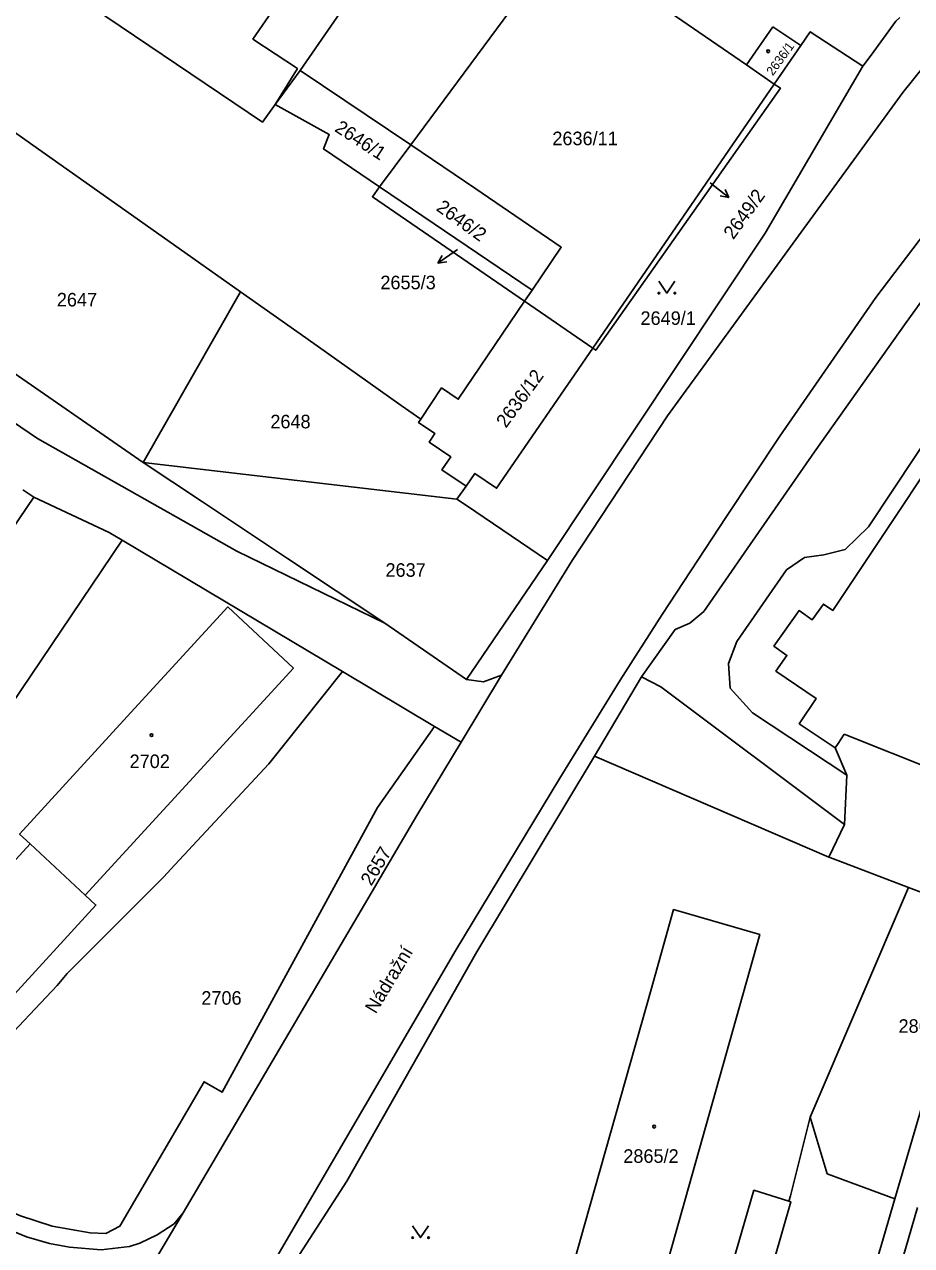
# Model space of a CAD drawing. Extents: x -527335 to -526256, y -1079142 to -1077836.
# Drawn here: x -527132.2 to -527020.7, y -1078877.1 to -1078723.7 of the extents above; entities that cross this region are included whole.
import ezdxf

# ---------------------------------------------------------------- set-up
doc = ezdxf.new("R2010")
doc.units = 0
for name, color, linetype in [('Hranice parcel', 7, 'Continuous'), ('Parcelní čísla', 7, 'Continuous'), ('Pop  PČ popisy', 7, 'Continuous'), ('Vnitřní kresba', 7, 'Continuous'), ('Značky budov', 7, 'Continuous'), ('Značky kultur', 7, 'Continuous')]:
    doc.layers.add(name, color=color, linetype=linetype)

msp = doc.modelspace()

# ---------------------------------------------------------------- linework, layer by layer
at = {"layer": 'Hranice parcel'}
for p, q in [((-527097.53, -1078729.48), (-527100.64, -1078733.75)), ((-527097.53, -1078729.48), (-527083.63, -1078738.83)), ((-527060.76, -1078764.37), (-527037.96, -1078731.19)), ((-527087.53, -1078744.11), (-527083.63, -1078738.83)), ((-527087.53, -1078744.11), (-527068.38, -1078757.06)), ((-527117.23, -1078778.72), (-527104.99, -1078757.3)), ((-527068.38, -1078757.06), (-527069.34, -1078758.47)), ((-527148.09, -1078757.41), (-527117.23, -1078778.72)), ((-527069.34, -1078758.47), (-527060.76, -1078764.37)), ((-527077.82, -1078783.31), (-527117.23, -1078778.72)), ((-527077.82, -1078783.31), (-527076.65, -1078781.68)), ((-527076.62, -1078805.97), (-527066.43, -1078791.03)), ((-527077.3, -1078813.84), (-527072.22, -1078805.43)), ((-527077.3, -1078813.84), (-527080.64, -1078811.86)), ((-527031.1, -1078828.29), (-527060.55, -1078815.59)), ((-527131.44, -1078826.61), (-527124.5, -1078833.07)), ((-527033.44, -1078860.94), (-527021.11, -1078832.09)), ((-526983.93, -1078846.24), (-527021.11, -1078832.09))]:
    msp.add_line(p, q, dxfattribs=at)
for points in [[(-527072.22, -1078805.43), (-527063.35, -1078791.03), (-527051.39, -1078772.86), (-527021.8, -1078732.24), (-527016.31, -1078725.38), (-526999.22, -1078705.77), (-526979.26, -1078684.5), (-526961.36, -1078666.17), (-526945.34, -1078649.61), (-526932.24, -1078641.62), (-526929.63, -1078639.61), (-526929.14, -1078637.23), (-526930.46, -1078635.68), (-526927.65, -1078633), (-526895.17, -1078602.34)], [(-527100.64, -1078733.75), (-527102.25, -1078735.96), (-527127.31, -1078719.02), (-527111.05, -1078694.45)], [(-527080.84, -1078705.04), (-527083.41, -1078706.65), (-527085.52, -1078706.27), (-527089.43, -1078704.54), (-527090.21, -1078705.74), (-527091.13, -1078707.66), (-527103.45, -1078725.55), (-527097.86, -1078729.26), (-527100.64, -1078733.75)], [(-527080.84, -1078705.04), (-527085.2, -1078711.65), (-527097.53, -1078729.48)], [(-527083.63, -1078738.83), (-527064.48, -1078712.94), (-527041.46, -1078728.79), (-527037.96, -1078731.19)], [(-527026.84, -1078728.96), (-527025.8, -1078727.55), (-527022.69, -1078723.31), (-527022.2, -1078722.85)], [(-526998.63, -1078724.92), (-527007.36, -1078735.07), (-527019.76, -1078750.86), (-527025.21, -1078757.99), (-527037.26, -1078775.41), (-527043.97, -1078785.5), (-527052.05, -1078797.8), (-527057.33, -1078806.06), (-527064.89, -1078818.36), (-527077.97, -1078839.97), (-527106.45, -1078888.73), (-527179.38, -1079013.92), (-527179.74, -1079015.3)], [(-527060.55, -1078815.59), (-527054.66, -1078805.64), (-527050.43, -1078799.71), (-527048.56, -1078798.89), (-527046.8, -1078797.42), (-527041.37, -1078789.55), (-527032.93, -1078777.37), (-527021.38, -1078761.15), (-527014.2, -1078751.18), (-527004.39, -1078737.66), (-526998.1, -1078729.59), (-526996.78, -1078727.49), (-526996.17, -1078726.12), (-526997.1, -1078724.79), (-526998.63, -1078724.92)], [(-527037.96, -1078731.19), (-527034.65, -1078726.37), (-527033.45, -1078724.63), (-527026.84, -1078728.96)], [(-527026.84, -1078728.96), (-527039.13, -1078749.94), (-527066.43, -1078791.03)], [(-527037.96, -1078731.19), (-527037.19, -1078731.69), (-527060.38, -1078764.63), (-527060.76, -1078764.37)], [(-527100.64, -1078733.75), (-527093.86, -1078737.51), (-527094.58, -1078739.34), (-527087.53, -1078744.11)], [(-527104.99, -1078757.3), (-527129.66, -1078739.88), (-527134.11, -1078736.73), (-527148.09, -1078757.41)], [(-527083.63, -1078738.83), (-527075.44, -1078744.34), (-527064.73, -1078751.68), (-527068.38, -1078757.06)], [(-527087.53, -1078744.11), (-527088.44, -1078745.34), (-527069.34, -1078758.47)], [(-527082.38, -1078773.28), (-527084.82, -1078771.55), (-527096.82, -1078763.08), (-527104.99, -1078757.3)], [(-527069.34, -1078758.47), (-527077.66, -1078770.78), (-527079.76, -1078769.36), (-527082.38, -1078773.28)], [(-527076.65, -1078781.68), (-527075.57, -1078780.1), (-527072.85, -1078781.96), (-527060.76, -1078764.37)], [(-527003.07, -1078773.49), (-527011.16, -1078768.09), (-527030.63, -1078797.3), (-527031.8, -1078796.49), (-527033.21, -1078798.48), (-527034.85, -1078797.32), (-527038.02, -1078801.77), (-527036.37, -1078802.94), (-527037.76, -1078804.91), (-527032.72, -1078808.35), (-527034.82, -1078811.52), (-527030.31, -1078814.54), (-527028.85, -1078818), (-527029.14, -1078824.18), (-527031.1, -1078828.29)], [(-527076.65, -1078781.68), (-527079.71, -1078779.62), (-527078.61, -1078778.01), (-527081.31, -1078776.16), (-527080.58, -1078775.08), (-527082.65, -1078773.68), (-527082.38, -1078773.28)], [(-527117.23, -1078778.72), (-527109.79, -1078783.67), (-527099.09, -1078790.78), (-527086.87, -1078798.91), (-527076.62, -1078805.97)], [(-527132.36, -1078782.16), (-527130.96, -1078783.09), (-527121.51, -1078787.51), (-527119.86, -1078788.49)], [(-527066.43, -1078791.03), (-527076.61, -1078784.13), (-527077.82, -1078783.31)], [(-527172.24, -1078856.19), (-527141.71, -1078814.86), (-527138.98, -1078816.71), (-527119.86, -1078788.49)], [(-527119.86, -1078788.49), (-527092.2, -1078804.98), (-527080.64, -1078811.86)], [(-527124.5, -1078833.07), (-527111.43, -1078818.8), (-527098.36, -1078804.54), (-527106.61, -1078796.85), (-527119.69, -1078811.12), (-527132.76, -1078825.39), (-527131.44, -1078826.61)], [(-527076.62, -1078805.97), (-527074.47, -1078806.26), (-527072.22, -1078805.43)], [(-527080.64, -1078811.86), (-527087.81, -1078822.05), (-527107.3, -1078857.78), (-527109.58, -1078856.49), (-527120.15, -1078874.63), (-527121.91, -1078875.54), (-527123.9, -1078875.45), (-527128.65, -1078874.62), (-527132.64, -1078873.34), (-527143.8, -1078868.59), (-527146.2, -1078867.57), (-527172.24, -1078856.19)], [(-527112.22, -1078872.94), (-527082.87, -1078823.07), (-527077.3, -1078813.84)], [(-527106.29, -1078891.74), (-527106.04, -1078891.29), (-527091.65, -1078868.97), (-527075.33, -1078840.18), (-527060.55, -1078815.59)], [(-527131.44, -1078826.61), (-527144.07, -1078840.4), (-527144.58, -1078840.95), (-527157.72, -1078855.29), (-527149.33, -1078862.84), (-527144.03, -1078857.05), (-527136.25, -1078848.56), (-527135.69, -1078847.95), (-527123.17, -1078834.29), (-527124.5, -1078833.07)], [(-527021.11, -1078832.09), (-527030.54, -1078828.5), (-527031.1, -1078828.29)], [(-527221.67, -1078833.78), (-527221.62, -1078835.3), (-527221.22, -1078836.2), (-527220.43, -1078836.77), (-527209.47, -1078841.8), (-527166.12, -1078861.35), (-527149.23, -1078868.84), (-527131.87, -1078875.96), (-527128.98, -1078876.81), (-527126.47, -1078877.28), (-527122.5, -1078877.6), (-527118.95, -1078877.18), (-527117.66, -1078876.76), (-527115.47, -1078875.73), (-527113.35, -1078874.31), (-527112.22, -1078872.94)], [(-527066.43, -1078890.98), (-527061.74, -1078874.35), (-527053.44, -1078844.9), (-527050.62, -1078834.87), (-527039.79, -1078837.98), (-527052.51, -1078883.15), (-527052.59, -1078883.43), (-527052.98, -1078884.85), (-527053.07, -1078885.16), (-527055.62, -1078894.2), (-527062.72, -1078892.18)], [(-527012.78, -1078858.89), (-527018.69, -1078857.04), (-527022.83, -1078871.21)], [(-527036.12, -1078871.48), (-527035.93, -1078870.81), (-527033.44, -1078860.94)], [(-527022.83, -1078871.21), (-527031.31, -1078868.03), (-527033.44, -1078860.94)], [(-527036.12, -1078871.48), (-527040.52, -1078870.12), (-527056.07, -1078923.59), (-527056.32, -1078925.44), (-527061.28, -1078942.36), (-527061.88, -1078943.73), (-527062.74, -1078944.48), (-527063.56, -1078944.86), (-527064.35, -1078944.84), (-527109.61, -1078934.05), (-527111.47, -1078933.13)], [(-526995.85, -1078962.29), (-527010.74, -1078958.5), (-527025.58, -1078954.47), (-527044.12, -1078949.38), (-527051.99, -1078948.07), (-527054.24, -1078947.27), (-527055.63, -1078946.46), (-527056.51, -1078945.37), (-527056.83, -1078944.49), (-527056.47, -1078943.22), (-527035.9, -1078871.55), (-527036.12, -1078871.48)], [(-527019.98, -1078872.28), (-527025.47, -1078891.17), (-527018.06, -1078893.37), (-527016.26, -1078887.19), (-527005.85, -1078890.36), (-527009.3, -1078901.58), (-527026.96, -1078896.29), (-527030.11, -1078907.12), (-527028.71, -1078907.46), (-527026.81, -1078901.4), (-527012.81, -1078905.7), (-527018.48, -1078924.2), (-527019.58, -1078927.78), (-527031.54, -1078924.07), (-527033.7, -1078923.4), (-527032.59, -1078919.86), (-527029.47, -1078909.9), (-527033.77, -1078908.6), (-527022.83, -1078871.21)], [(-527131.27, -1078905.61), (-527124.93, -1078894.36), (-527124.67, -1078892.26), (-527123.81, -1078892.07), (-527117.09, -1078881.21), (-527112.22, -1078872.94)]]:
    msp.add_lwpolyline(points, dxfattribs=at)
at = {"layer": 'Pop  PČ popisy'}
for p, q in [((-527046.02, -1078743.59), (-527043.66, -1078745.44)), ((-527043.66, -1078745.44), (-527044.14, -1078744.43)), ((-527043.66, -1078745.44), (-527044.75, -1078745.22)), ((-527077.76, -1078751.97), (-527080.22, -1078753.69)), ((-527080.22, -1078753.69), (-527079.69, -1078752.71)), ((-527080.22, -1078753.69), (-527079.11, -1078753.53))]:
    msp.add_line(p, q, dxfattribs=at)
at = {"layer": 'Vnitřní kresba'}
for p, q in [((-527206.11, -1078724.43), (-527130.49, -1078775.7)), ((-527038.14, -1078723.99), (-527041.46, -1078728.79)), ((-527034.65, -1078726.37), (-527038.14, -1078723.99)), ((-527026.13, -1078786.78), (-527013.46, -1078767.65)), ((-527130.49, -1078775.7), (-527105.49, -1078789.87)), ((-527178.67, -1078853.11), (-527130.96, -1078783.09)), ((-527029.05, -1078789.66), (-527026.13, -1078786.78)), ((-527105.49, -1078789.87), (-527086.87, -1078798.91)), ((-527036.42, -1078792.21), (-527034.18, -1078790.66)), ((-527034.18, -1078790.66), (-527031.73, -1078790.3)), ((-527031.73, -1078790.3), (-527029.05, -1078789.66)), ((-527042.65, -1078801.19), (-527036.42, -1078792.21)), ((-527043.72, -1078803.96), (-527042.65, -1078801.19)), ((-527043.51, -1078807.08), (-527043.72, -1078803.96)), ((-527092.2, -1078804.98), (-527099.77, -1078814.45)), ((-527054.66, -1078805.64), (-527052.21, -1078806.89)), ((-527052.21, -1078806.89), (-527029.14, -1078824.18)), ((-527040.69, -1078810.14), (-527043.51, -1078807.08)), ((-527028.85, -1078818), (-527040.69, -1078810.14)), ((-527029.95, -1078814), (-527030.31, -1078814.54)), ((-527029.95, -1078814), (-527029.19, -1078812.84)), ((-527029.19, -1078812.84), (-527005.06, -1078822.46)), ((-527101.43, -1078816.55), (-527099.77, -1078814.45)), ((-527113.27, -1078829.25), (-527101.43, -1078816.55)), ((-527114.7, -1078830.81), (-527113.27, -1078829.25)), ((-527126.76, -1078842.91), (-527114.7, -1078830.81)), ((-527128.03, -1078844.4), (-527126.76, -1078842.91)), ((-527137.41, -1078854.29), (-527128.03, -1078844.4))]:
    msp.add_line(p, q, dxfattribs=at)
at = {"layer": 'Značky budov'}
for centre in [(-527038.74, -1078727.08), (-527116.18, -1078812.95), (-527053.06, -1078862.12)]:
    msp.add_circle(centre, 0.175, dxfattribs=at)
at = {"layer": 'Značky kultur'}
for points in [[(-527052.46, -1078755.95), (-527051.46, -1078757.45), (-527050.46, -1078755.95)], [(-527083.39, -1078874.56), (-527082.39, -1078876.06), (-527081.39, -1078874.56)]]:
    msp.add_lwpolyline(points, dxfattribs=at)
for centre in [(-527052.46, -1078757.45), (-527050.46, -1078757.45), (-527083.39, -1078876.06), (-527081.39, -1078876.06)]:
    msp.add_circle(centre, 0.1, dxfattribs=at)

# ---------------------------------------------------------------- texts
at = {"layer": 'Parcelní čísla'}
for s, height, rotation, p in [('2636/1', 1.139, 54, (-527038.14, -1078730.22)), ('2646/1', 1.7, 327, (-527093.3, -1078737.05)), ('2649/2', 1.7, 54, (-527043.11, -1078750.81)), ('2646/2', 1.7, 324, (-527080.54, -1078746.97)), ('2636/12', 1.7, 54, (-527071.66, -1078774.48)), ('2657', 1.7, 59, (-527088.58, -1078831.99))]:
    msp.add_text(s, height=height, rotation=rotation, dxfattribs=at).set_placement(p)
for s, p in [('2636/11', (-527065.84, -1078738.87)), ('2655/3', (-527087.44, -1078756.96)), ('2647', (-527128.08, -1078759.12)), ('2649/1', (-527054.77, -1078761.44)), ('2648', (-527101.26, -1078774.43)), ('2637', (-527086.8, -1078793.07)), ('2702', (-527118.94, -1078817.09)), ('2706', (-527109.93, -1078846.81)), ('2868/1', (-527022.36, -1078850.34)), ('2865/2', (-527056.93, -1078866.67))]:
    msp.add_text(s, height=1.7, dxfattribs=at).set_placement(p)
at = {"layer": 'Pop  PČ popisy'}
msp.add_text('Nádražní', height=1.7, rotation=59, dxfattribs=at).set_placement((-527088.02, -1078848.05))

doc.saveas('drawing.dxf')
